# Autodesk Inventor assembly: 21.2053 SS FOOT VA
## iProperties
Created: 2011-11
Part Number: 21.2053 SS FOOT VA
Document SubType Name: Assembly
Designer: Administrator
Mass: 93.4738 g
Surface Area: 103.045 cm^2
Volume: 17.2924 cm^3
Density: 5.4055 g/cm^3
Author: Administrator
